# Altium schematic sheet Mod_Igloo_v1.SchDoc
size A4
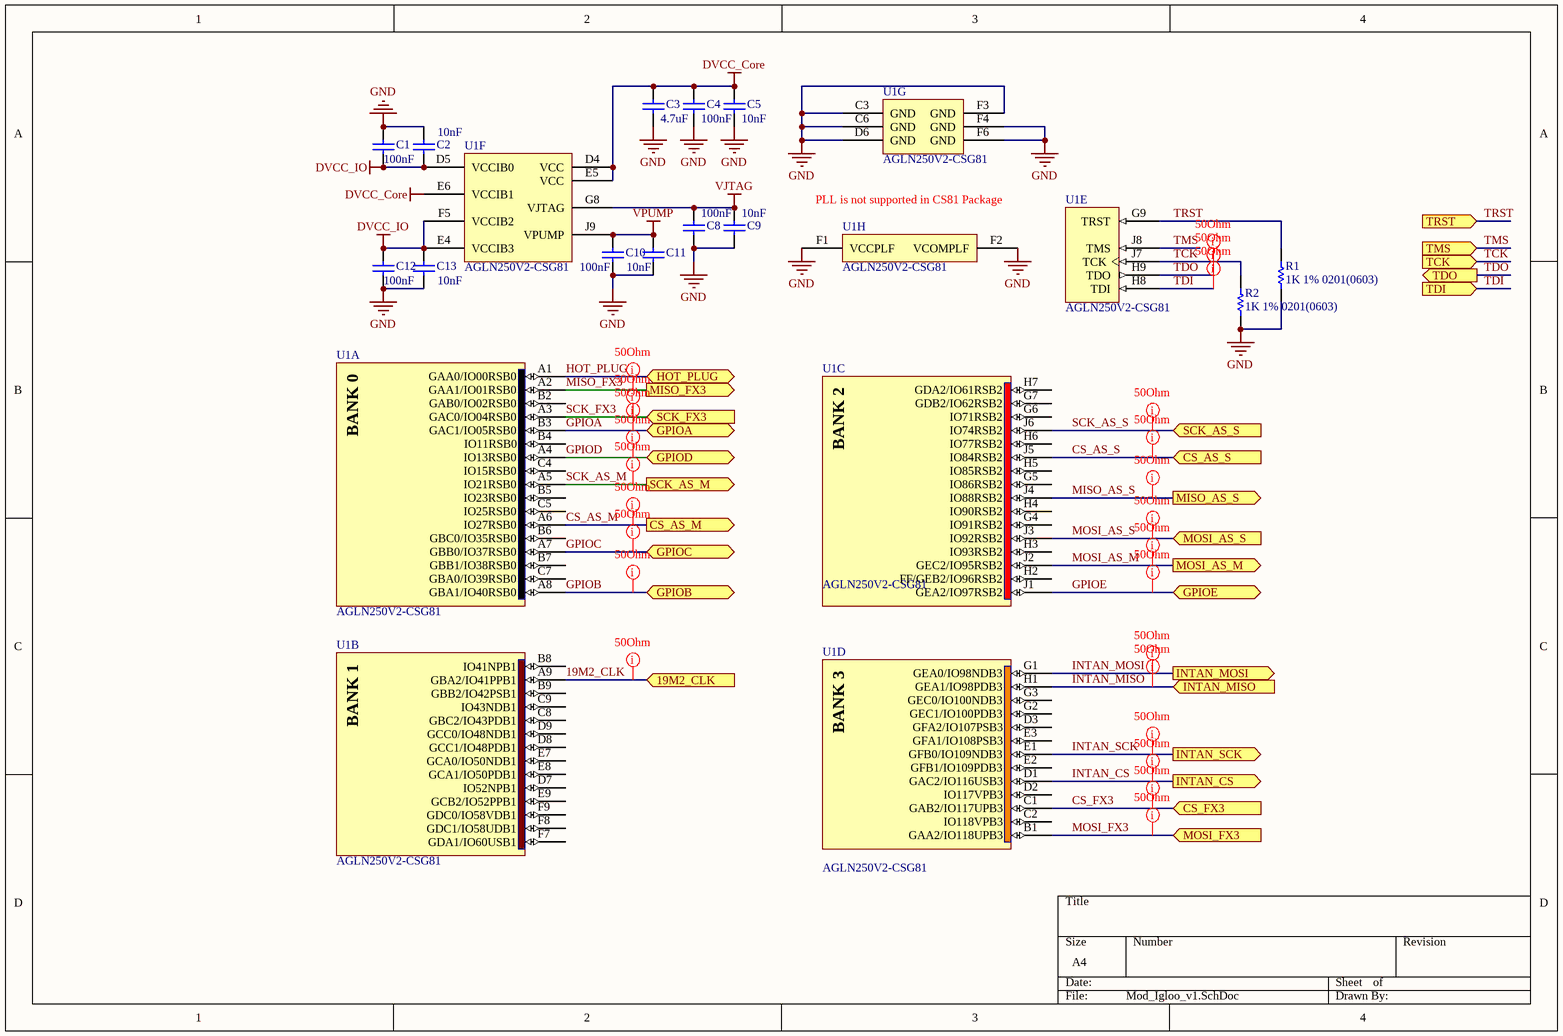
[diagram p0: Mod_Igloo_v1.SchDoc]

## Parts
(Parts that share a designator on the sheet are numbered #1, #2 ... from top to bottom, then left to right.)
C1  value 100nF  [CAPC0201(0603)33_N]  (hidden comment: CAP 100nF 16V 0201(0603))
C2  value 10nF  [CAPC0201(0603)33_L]  (hidden comment: CAP 10nF 16V 0201(0603))
C3  value 4.7uF  [CAPC0402(1005)60_N]  (hidden comment: CAP 4.7uF 6.3V 0402(1005))
C4  value 100nF  [CAPC0201(0603)33_N]  (hidden comment: CAP 100nF 16V 0201(0603))
C5  value 10nF  [CAPC0201(0603)33_L]  (hidden comment: CAP 10nF 16V 0201(0603))
C8  value 100nF  [CAPC0201(0603)33_N]  (hidden comment: CAP 100nF 16V 0201(0603))
C9  value 10nF  [CAPC0201(0603)33_L]  (hidden comment: CAP 10nF 16V 0201(0603))
C10  value 100nF  [CAPC0201(0603)33_N]  (hidden comment: CAP 100nF 16V 0201(0603))
C11  value 10nF  [CAPC0201(0603)33_L]  (hidden comment: CAP 10nF 16V 0201(0603))
C12  value 100nF  [CAPC0201(0603)33_N]  (hidden comment: CAP 100nF 16V 0201(0603))
C13  value 10nF  [CAPC0201(0603)33_L]  (hidden comment: CAP 10nF 16V 0201(0603))
R1  1K 1% 0201(0603)  [RESC0201(0603)_L]
R2  1K 1% 0201(0603)  [RESC0201(0603)_L]
U1#1  AGLN250V2-CSG81  [CS81]  (parts C,D,E of 8)
U1#2  AGLN250V2-CSG81  [CS81]  (parts A,B,F,G,H of 8)

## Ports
19M2_CLK (in), CS_AS_M (out), CS_AS_S (in), CS_FX3 (in), GPIOA, GPIOB, GPIOC, GPIOD, GPIOE, HOT_PLUG, INTAN_CS (out), INTAN_MISO (in), INTAN_MOSI (out), INTAN_SCK (out), MISO_AS_S (out), MISO_FX3 (out), MOSI_AS_M (out), MOSI_AS_S (in), MOSI_FX3 (in), SCK_AS_M (out), SCK_AS_S (in), SCK_FX3 (in), TCK (in), TDI (in), TDO (out), TMS (in), TRST (in)

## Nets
DVCC_Core: C3.1 C4.2 C5.2 U1#2.D4(VCC) U1#2.E5(VCC) U1#2.E6(VCCIB1)
DVCC_IO: C1.1 C2.1 C12.2 C13.1 U1#2.D5(VCCIB0) U1#2.E4(VCCIB3) U1#2.F5(VCCIB2)
GND: C1.2 C2.2 C3.2 C4.1 C5.1 C8.1 C9.1 C10.1 C11.1 C12.1 C13.2 R1.2 R2.2 U1#2.C3(GND) U1#2.C6(GND) U1#2.D6(GND) U1#2.F1(VCCPLF) U1#2.F2(VCOMPLF) U1#2.F3(GND) U1#2.F4(GND) U1#2.F6(GND)
VJTAG: C8.2 C9.2 U1#2.G8(VJTAG)
VPUMP: C10.2 C11.2 U1#2.J9(VPUMP)
19M2_CLK: U1#2.A9(GBA2/IO41PPB1) ; port 19M2_CLK
CS_AS_M: U1#2.A6(IO27RSB0) ; port CS_AS_M
CS_AS_S: U1#1.J5(IO84RSB2) ; port CS_AS_S
CS_FX3: U1#1.C1(GAB2/IO117UPB3) ; port CS_FX3
GPIOA: U1#2.B3(GAC1/IO05RSB0) ; port GPIOA
GPIOB: U1#2.A8(GBA1/IO40RSB0) ; port GPIOB
GPIOC: U1#2.A7(GBB0/IO37RSB0) ; port GPIOC
GPIOD: U1#2.A4(IO13RSB0) ; port GPIOD
GPIOE: U1#1.J1(GEA2/IO97RSB2) ; port GPIOE
HOT_PLUG: U1#2.A1(GAA0/IO00RSB0) ; port HOT_PLUG
INTAN_CS: U1#1.D1(GAC2/IO116USB3) ; port INTAN_CS
INTAN_MISO: U1#1.H1(GEA1/IO98PDB3) ; port INTAN_MISO
INTAN_MOSI: U1#1.G1(GEA0/IO98NDB3) ; port INTAN_MOSI
INTAN_SCK: U1#1.E1(GFB0/IO109NDB3) ; port INTAN_SCK
MISO_AS_S: U1#1.J4(IO88RSB2) ; port MISO_AS_S
MISO_FX3: U1#2.A2(GAA1/IO01RSB0) ; port MISO_FX3
MOSI_AS_M: U1#1.J2(GEC2/IO95RSB2) ; port MOSI_AS_M
MOSI_AS_S: U1#1.J3(IO92RSB2) ; port MOSI_AS_S
MOSI_FX3: U1#1.B1(GAA2/IO118UPB3) ; port MOSI_FX3
SCK_AS_M: U1#2.A5(IO21RSB0) ; port SCK_AS_M
SCK_AS_S: U1#1.J6(IO74RSB2) ; port SCK_AS_S
SCK_FX3: U1#2.A3(GAC0/IO04RSB0) ; port SCK_FX3
TCK: R2.1 U1#1.J7(TCK) ; port TCK
TDI: U1#1.H8(TDI) ; port TDI
TDO: U1#1.H9(TDO) ; port TDO
TMS: U1#1.J8(TMS) ; port TMS
TRST: R1.1 U1#1.G9(TRST) ; port TRST

Not connected (* = marked no-connect by the designer): U1#1 C2(IO118VPB3) D2(IO117VPB3) D3(GFA2/IO107PSB3) E2(GFB1/IO109PDB3) E3(GFA1/IO108PSB3) G2(GEC1/IO100PDB3) G3(GEC0/IO100NDB3) G4(IO91RSB2) G5(IO86RSB2) G6(IO71RSB2) G7(GDB2/IO62RSB2) H2(FF/GEB2/IO96RSB2) H3(IO93RSB2) H4(IO90RSB2) H5(IO85RSB2) H6(IO77RSB2) H7(GDA2/IO61RSB2); U1#2 B2(GAB0/IO02RSB0) B4(IO11RSB0) B5(IO23RSB0) B6(GBC0/IO35RSB0) B7(GBB1/IO38RSB0) B8(IO41NPB1) B9(GBB2/IO42PSB1) C4(IO15RSB0) C5(IO25RSB0) C7(GBA0/IO39RSB0) C8(GBC2/IO43PDB1) C9(IO43NDB1) D7(IO52NPB1) D8(GCC1/IO48PDB1) D9(GCC0/IO48NDB1) E7(GCA0/IO50NDB1) E8(GCA1/IO50PDB1) E9(GCB2/IO52PPB1) F7(GDA1/IO60USB1) F8(GDC1/IO58UDB1) F9(GDC0/IO58VDB1)

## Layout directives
net class 50Ohm: 19M2_CLK, CS_AS_M, CS_AS_S, CS_FX3, GPIOA, GPIOB, GPIOC, GPIOD, GPIOE, INTAN_CS, INTAN_MISO, INTAN_MOSI, INTAN_SCK, MISO_AS_S, MISO_FX3, MOSI_AS_M, MOSI_AS_S, MOSI_FX3, SCK_AS_M, SCK_AS_S, SCK_FX3, TCK, TDI, TDO

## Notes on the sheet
- (near U1#2) PLL is not supported in CS81 Package

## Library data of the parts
C1 C4 C8 C10 C12 = CMP-1033-00663-1: CAP 100nF 16V Â±10% 0201 (0603 Metric) Thickness 0.33mm SMD; Case-Metric: 0603; Case-EIA: 0201
C2 C5 C9 C11 C13 = CMP-1033-00642-1: CAP 10nF 16V Â±10% 0201 (0603 Metric) Thickness 0.33mm SMD; Case-Metric: 0603; Case-EIA: 0201
C3 = CMP-1034-02137-1: CAP 4.7uF 6.3V Â±20% 0402 (1005 Metric) Thickness 0.6mm SMD; Case-Metric: 1005; Case-EIA: 0402
R1 R2 = CMP-1010-00416-1: 1K 0.05W 1% 0201 (0603 Metric)  SMD; Value: 1000.00 Ohm; Case-Metric: 0603; Case-EIA: 0201
U1#1 U1#2 = CMP-0101-00037-1: IGLOO nano Low-Power Flash 1.2 to 1.5V FPGA with Flash*Freeze, 60 User IOs, 250K System Gates, 1Kbit Flash ROM, 81-Pin CSP, Commercial Grade, Pb-Free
